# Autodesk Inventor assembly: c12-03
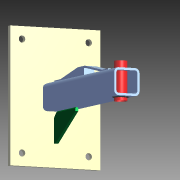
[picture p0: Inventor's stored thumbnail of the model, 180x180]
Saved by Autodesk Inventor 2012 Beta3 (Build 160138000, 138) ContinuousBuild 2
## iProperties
Created: 2011-01
Part Number: c12-03
Document SubType Name: Weldment
Designer: Beta-8540w
Weld Material: Welded Steel Mild
_SolveAssemblyDoc: Frame Generator Solve Assembly
_Version: 15.0.0
Author: Beta-8540w
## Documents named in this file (5)
- C:\Inventor 2012 Essentials\Assemblies\Chapter 12\c12-03.iam
- C:\Inventor 2012 Essentials\Parts\Chapter 12\c12-01.ipt
- C:\Inventor 2012 Essentials\Parts\Chapter 12\c12-02.ipt
- C:\Inventor 2012 Essentials\Assemblies\Chapter 12\Frame\Frame c12-01.iam
- C:\Inventor 2012 Essentials\Parts\Chapter 12\c12-03.ipt
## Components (4 placed, 4 different names)
1. c12-01:1 — Mate:2
2. c12-02:1 — Flush:1
3. Frame c12-01:1 [sub-assembly] — Mate:3
4. c12-03:1 — Mate:1, Mate:2, Mate:3
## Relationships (4: Mate 3, Flush 1)
- Flush:1: c12-02:1
- Mate:1: c12-03:1
- Mate:2: c12-01:1 ↔ c12-03:1
- Mate:3: Frame c12-01:1 ↔ c12-03:1
